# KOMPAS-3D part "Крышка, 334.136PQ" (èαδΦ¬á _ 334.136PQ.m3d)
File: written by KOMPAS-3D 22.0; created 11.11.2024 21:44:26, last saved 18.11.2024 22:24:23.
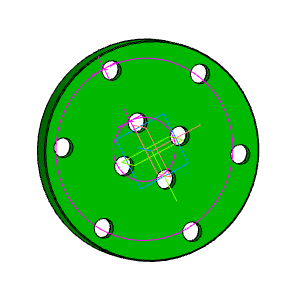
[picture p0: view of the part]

Document properties: Автор: aleksander.larionov.10@gmail.com; Полное имя файла: C:\Мои папки\Работа\Крышки, фланцы\334.136PQ\Крышка _ 334.136PQ.m3d

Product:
- Part/product: Крышка  | designation 334.136PQ
    Материал: Сталь 45 ГОСТ 1050-2013 (density 7810 kg/m3)
    Масса: 5.920024

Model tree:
1. Эскиз:1
2. Элемент выдавливания:1
     Расстояние 1 = 28
3. Эскиз:2  (with: Элемент выдавливания:1)
4. Отверстие:1  (with: Элемент выдавливания:1)
     Глубина выреза = 28; Диаметр отверстия = 18; Угол конуса дна = 118; Расстояние 1 = 82.5; Диаметр цековки = 26; Глубина цековки = 18
5. Отверстие:2  (with: Элемент выдавливания:1)
     Глубина выреза = 28; Диаметр отверстия = 18; Угол конуса дна = 118; Расстояние 1 = 29; Диаметр цековки = 26; Глубина цековки = 18
6. Массив по концентрической сетке:1  (with: Отверстие:2)  (4 pattern instances)
     Шаг 2 = 360
7. Массив по концентрической сетке:2  (with: Отверстие:1)  (6 pattern instances)
     Шаг 2 = 360
8. Фаска:1  (with: Элемент выдавливания:1)  (labels: Сталь 45 ГОСТ 1050-2013)
     Угол = 45; Длина 1 = 1; Длина 2 = 1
